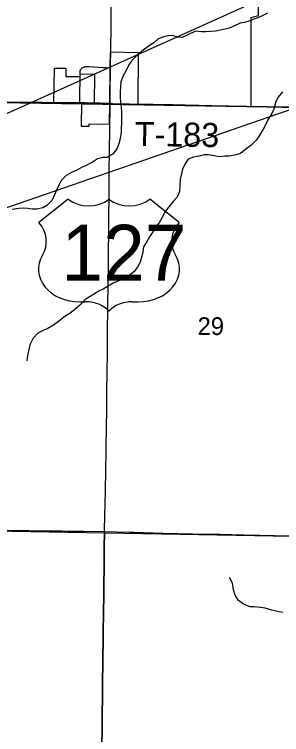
# Model space of a CAD drawing. Extents: x 0 to 34, y 0 to 22.
# Drawn here: x 6.718 to 7.346, y 15.064 to 16.761 of the extents above; entities that cross this region are included whole.
import ezdxf

# ---------------------------------------------------------------- set-up
doc = ezdxf.new("R2010")
doc.units = 0
for name, color, linetype in [('GM_X_Corporation', 7, 'Continuous'), ('GM_X_Minor_River', 7, 'Continuous'), ('GM_X_Section_Text', 7, 'Continuous'), ('GM_X_State_Route', 7, 'Continuous'), ('GM_X_Township_Road', 7, 'Continuous'), ('GM_X_Township_Road_Text', 7, 'Continuous'), ('GM_X_US_Location', 7, 'Continuous'), ('GM_X_US_Route', 7, 'Continuous'), ('GM_X_US_Shield', 7, 'Continuous'), ('SH_Data', 7, 'Continuous')]:
    doc.layers.add(name, color=color, linetype=linetype)

msp = doc.modelspace()

# ---------------------------------------------------------------- linework, layer by layer
at = {"layer": 'GM_X_Corporation'}
for points in [[(6.7004, 17.5689), (7.7016, 17.5373), (7.6999, 16.5369), (6.6829, 16.5538)], [(6.6829, 16.5538), (7.6999, 16.5369), (7.6779, 15.5253), (6.6666, 15.5439)]]:
    msp.add_lwpolyline(points, close=True, dxfattribs=at)
msp.add_lwpolyline([(6.6248, 16.5554), (6.8105, 16.5532), (6.8118, 16.6347), (6.839, 16.6342), (6.8387, 16.6152), (6.865, 16.6148), (6.8722, 16.6146), (6.8723, 16.621), (6.906, 16.6204), (6.905, 16.5515), (6.8756, 16.552), (6.875, 16.498), (6.8939, 16.4977), (6.894, 16.5034), (6.9414, 16.5025), (6.9419, 16.5525), (6.943, 16.6361), (6.9435, 16.6727), (7.0088, 16.6713), (7.0085, 16.5495), (7.2751, 16.5441), (7.2751, 16.7536), (7.2917, 16.7587), (7.2924, 16.7953)], dxfattribs=at)
at = {"layer": 'GM_X_Minor_River'}
for points in [[(7.313, 16.7641), (7.3004, 16.7579), (7.2908, 16.7535), (7.2809, 16.7499), (7.2713, 16.7463), (7.2588, 16.7424), (7.2492, 16.7403), (7.2355, 16.7345), (7.2229, 16.729), (7.2133, 16.7266), (7.2015, 16.7242), (7.1905, 16.7217), (7.1798, 16.7208), (7.1681, 16.7203), (7.1571, 16.7205), (7.1438, 16.7215), (7.1255, 16.7131), (7.1121, 16.7065), (7.1019, 16.7079), (7.089, 16.7116), (7.0788, 16.711), (7.0685, 16.7085), (7.0555, 16.7027), (7.0459, 16.6946), (7.0328, 16.6857), (7.0205, 16.6772), (7.0085, 16.6665), (6.9938, 16.6523), (6.9872, 16.6422), (6.9805, 16.6291), (6.9734, 16.6163), (6.9679, 16.6027), (6.9672, 16.591), (6.9666, 16.5781), (6.9668, 16.566), (6.9677, 16.5534), (6.9686, 16.5424), (6.9699, 16.5299), (6.97, 16.5173), (6.9697, 16.5044), (6.9692, 16.4942), (6.9686, 16.4836), (6.9676, 16.4738), (6.9639, 16.4587), (6.9587, 16.4443), (6.9498, 16.4331), (6.936, 16.4243), (6.9261, 16.4237), (6.9135, 16.4213), (6.9016, 16.4128), (6.8867, 16.4051), (6.8771, 16.4015), (6.8645, 16.3946), (6.8522, 16.3884), (6.8396, 16.3818), (6.8276, 16.3695), (6.8221, 16.359), (6.8169, 16.3469), (6.8122, 16.336), (6.8062, 16.3233), (6.7942, 16.3106), (6.7843, 16.3055), (6.7702, 16.3023), (6.7596, 16.3025), (6.749, 16.3043), (6.738, 16.3049), (6.7285, 16.3039), (6.7121, 16.3016)], [(7.3489, 16.579), (7.338, 16.5663), (7.3329, 16.5562), (7.328, 16.5377), (7.3236, 16.5275), (7.3142, 16.5125), (7.3063, 16.4964), (7.3005, 16.4866), (7.2934, 16.475), (7.2868, 16.4649), (7.274, 16.4526), (7.2625, 16.4441), (7.2494, 16.4334), (7.2364, 16.4294), (7.2227, 16.427), (7.2132, 16.4272), (7.2011, 16.4256), (7.1871, 16.4277), (7.1742, 16.4303), (7.164, 16.4305), (7.1526, 16.4273), (7.1392, 16.4245), (7.1262, 16.4198), (7.1177, 16.4071), (7.1133, 16.3969), (7.11, 16.3826)], [(7.11, 16.3826), (7.1075, 16.3724), (7.1072, 16.3584), (7.1062, 16.3443), (7.1006, 16.3304), (7.091, 16.3207), (7.0812, 16.3076), (7.0711, 16.2942), (7.066, 16.2844), (7.0589, 16.2717), (7.0519, 16.2619), (7.0355, 16.2372), (7.0284, 16.2248), (7.0214, 16.2136), (7.02, 16.2015), (7.0175, 16.1913), (7.0139, 16.1773), (7.0076, 16.1657), (6.9994, 16.1556), (6.9867, 16.1456), (6.9741, 16.139), (6.9633, 16.1332), (6.9503, 16.1277), (6.9369, 16.1204), (6.9262, 16.1138), (6.9166, 16.109), (6.9062, 16.1032), (6.8959, 16.0969), (6.8836, 16.0888), (6.8716, 16.0762), (6.8593, 16.0654), (6.8462, 16.0558), (6.8362, 16.0492), (6.8216, 16.0377), (6.81, 16.0292), (6.7966, 16.0215), (6.7866, 16.0171), (6.7732, 16.0102), (6.762, 15.9983), (6.7541, 15.9829), (6.7513, 15.9719), (6.7487, 15.9579), (6.7473, 15.9447)], [(7.2333, 15.4054), (7.2305, 15.4213), (7.224, 15.4347)], [(7.3494, 15.3519), (7.3366, 15.3544), (7.3234, 15.3577), (7.3079, 15.3618), (7.2969, 15.3639), (7.2818, 15.365), (7.2723, 15.3652), (7.258, 15.3707), (7.2453, 15.3805), (7.2372, 15.3931), (7.2333, 15.4054)]]:
    msp.add_lwpolyline(points, dxfattribs=at)
at = {"layer": 'GM_X_State_Route'}
msp.add_line((6.9423, 16.5018), (6.9428, 16.5344), dxfattribs=at)
for points in [[(6.9456, 16.7596), (6.9456, 16.7606), (6.9457, 16.7839), (6.9458, 16.7879)], [(6.9443, 16.6727), (6.9445, 16.6912), (6.945, 16.7184), (6.9452, 16.7457), (6.9456, 16.7596)], [(6.9438, 16.6354), (6.9439, 16.6432), (6.9443, 16.6717), (6.9443, 16.6727)], [(6.9428, 16.5518), (6.9428, 16.5537), (6.9432, 16.5885), (6.9437, 16.622), (6.9438, 16.6354)], [(6.9428, 16.5344), (6.9428, 16.5394), (6.9428, 16.5518)], [(6.9389, 16.1755), (6.9389, 16.1785), (6.94, 16.2717), (6.9402, 16.2984), (6.9405, 16.3177), (6.9407, 16.3631), (6.9409, 16.373), (6.9409, 16.4017), (6.9413, 16.4296), (6.9416, 16.451), (6.942, 16.4794), (6.9422, 16.4977), (6.9423, 16.5018)], [(6.9379, 16.0956), (6.938, 16.1045), (6.9389, 16.1755)], [(6.9296, 15.5426), (6.9306, 15.5826), (6.9311, 15.6043), (6.9325, 15.6823), (6.9335, 15.7364), (6.9344, 15.793), (6.9348, 15.8238), (6.9352, 15.8524), (6.9355, 15.8769), (6.936, 15.9136), (6.9365, 15.9685), (6.9368, 15.9973), (6.9371, 16.0273), (6.9376, 16.056), (6.9379, 16.0956)], [(6.675, 15.5461), (6.701, 15.5459), (6.7352, 15.5455), (6.7514, 15.545), (6.7657, 15.5447), (6.7959, 15.5444), (6.8145, 15.5442), (6.8298, 15.5441)], [(6.8298, 15.5441), (6.837, 15.544), (6.88, 15.5437), (6.9296, 15.5426)], [(6.9296, 15.5426), (6.9292, 15.504), (6.9286, 15.4555), (6.9281, 15.4219), (6.9279, 15.3859), (6.9275, 15.3598), (6.9258, 15.2342), (6.9253, 15.1863), (6.9239, 15.0781), (6.9236, 15.0402), (6.923, 14.9967), (6.9221, 14.9352), (6.9218, 14.8979), (6.9215, 14.8823), (6.921, 14.8425), (6.9207, 14.817), (6.9205, 14.7947), (6.9203, 14.7804)]]:
    msp.add_lwpolyline(points, dxfattribs=at)
at = {"layer": 'GM_X_Township_Road'}
msp.add_line((6.8718, 16.5535), (6.8758, 16.5535), dxfattribs=at)
for points in [[(6.8722, 16.6139), (6.8722, 16.6252), (6.8725, 16.6276), (6.8728, 16.6289), (6.8732, 16.63), (6.8736, 16.6308), (6.874, 16.6316), (6.8748, 16.6327), (6.8756, 16.6336), (6.8763, 16.6343), (6.8774, 16.6352)], [(6.8774, 16.6352), (6.8793, 16.6363), (6.8806, 16.637), (6.8817, 16.6375), (6.8827, 16.6378), (6.8834, 16.638), (6.885, 16.6382), (6.8871, 16.6384), (6.8933, 16.6384), (6.9039, 16.6379), (6.9268, 16.6362), (6.9336, 16.6359), (6.9438, 16.6354)], [(6.8718, 16.5535), (6.8718, 16.5593), (6.8718, 16.5768), (6.8722, 16.6055), (6.8722, 16.6139)], [(6.6248, 16.5547), (6.6387, 16.5547), (6.6598, 16.5547), (6.7003, 16.5546), (6.7394, 16.5545), (6.7833, 16.5541), (6.8106, 16.5539)], [(6.8106, 16.5539), (6.8442, 16.5536), (6.8718, 16.5535)], [(6.8758, 16.5535), (6.8836, 16.5534), (6.9052, 16.5528), (6.9061, 16.5528)], [(6.9061, 16.5528), (6.9123, 16.5527), (6.9198, 16.5526), (6.9383, 16.5519), (6.9428, 16.5518)], [(6.9428, 16.5518), (6.9486, 16.5512), (6.9528, 16.5509), (6.9573, 16.5507), (6.9883, 16.5502), (7.0085, 16.5499)], [(7.0085, 16.5499), (7.016, 16.5497), (7.044, 16.5494), (7.0906, 16.5486), (7.1192, 16.548), (7.1514, 16.5472), (7.1833, 16.5467), (7.2581, 16.545), (7.2752, 16.5446)], [(7.2752, 16.5446), (7.3029, 16.5439), (7.3259, 16.5435), (7.3477, 16.5429), (7.4055, 16.5418), (7.4602, 16.5405), (7.5248, 16.5387)]]:
    msp.add_lwpolyline(points, dxfattribs=at)
at = {"layer": 'GM_X_US_Route'}
for p, q in [((6.9423, 16.5018), (6.9428, 16.5344)), ((6.9296, 15.5426), (6.988, 15.5414))]:
    msp.add_line(p, q, dxfattribs=at)
for points in [[(6.9456, 16.7596), (6.9456, 16.7606), (6.9457, 16.7839), (6.9458, 16.7879)], [(6.9443, 16.6727), (6.9445, 16.6912), (6.945, 16.7184), (6.9452, 16.7457), (6.9456, 16.7596)], [(6.9438, 16.6354), (6.9439, 16.6432), (6.9443, 16.6717), (6.9443, 16.6727)], [(6.9428, 16.5518), (6.9428, 16.5537), (6.9432, 16.5885), (6.9437, 16.622), (6.9438, 16.6354)], [(6.9428, 16.5344), (6.9428, 16.5394), (6.9428, 16.5518)], [(6.9389, 16.1755), (6.9389, 16.1785), (6.94, 16.2717), (6.9402, 16.2984), (6.9405, 16.3177), (6.9407, 16.3631), (6.9409, 16.373), (6.9409, 16.4017), (6.9413, 16.4296), (6.9416, 16.451), (6.942, 16.4794), (6.9422, 16.4977), (6.9423, 16.5018)], [(6.9379, 16.0956), (6.938, 16.1045), (6.9389, 16.1755)], [(6.9296, 15.5426), (6.9306, 15.5826), (6.9311, 15.6043), (6.9325, 15.6823), (6.9335, 15.7364), (6.9344, 15.793), (6.9348, 15.8238), (6.9352, 15.8524), (6.9355, 15.8769), (6.936, 15.9136), (6.9365, 15.9685), (6.9368, 15.9973), (6.9371, 16.0273), (6.9376, 16.056), (6.9379, 16.0956)], [(6.675, 15.5461), (6.701, 15.5459), (6.7352, 15.5455), (6.7514, 15.545), (6.7657, 15.5447), (6.7959, 15.5444), (6.8145, 15.5442), (6.8298, 15.5441)], [(6.8298, 15.5441), (6.837, 15.544), (6.88, 15.5437), (6.9296, 15.5426)], [(6.9203, 14.7804), (6.9205, 14.7947), (6.9207, 14.817), (6.921, 14.8425), (6.9215, 14.8823), (6.9218, 14.8979), (6.9221, 14.9352), (6.923, 14.9967), (6.9236, 15.0402), (6.9239, 15.0781), (6.9253, 15.1863), (6.9258, 15.2342), (6.9275, 15.3598), (6.9279, 15.3859), (6.9281, 15.4219), (6.9286, 15.4555), (6.9292, 15.504), (6.9296, 15.5426)], [(6.988, 15.5414), (6.9991, 15.5412), (7.068, 15.5392), (7.137, 15.5374), (7.201, 15.5362), (7.2582, 15.535), (7.403, 15.5321)]]:
    msp.add_lwpolyline(points, dxfattribs=at)
at = {"layer": 'GM_X_US_Shield'}
for p, q in [((6.8441, 16.3259), (6.7754, 16.2709)), ((7.105, 16.2709), (7.0363, 16.3259)), ((6.8716, 16.0842), (6.8853, 16.0842)), ((6.9951, 16.0842), (7.0089, 16.0842))]:
    msp.add_line(p, q, dxfattribs=at)
for centre, major_axis, start_param, end_param in [((6.8922, 16.3651), (-0.0687, 0), 0.795399, 2.346194), ((6.9883, 16.3651), (-0.0687, 0), 0.795399, 2.346194), ((6.6967, 16.2268), (0.0961, 0), 5.838949, 6.894067), ((7.1838, 16.2268), (-0.0961, 0), 5.672304, 6.727422), ((6.8705, 16.1611), (0.0961, 0), 2.702327, 4.723529), ((7.01, 16.1611), (-0.0961, 0), 1.559657, 3.580859), ((6.8853, 16.0292), (-0.0687, 0), 3.785094, 4.712389), ((6.9951, 16.0292), (-0.0687, 0), 4.712389, 5.639684)]:
    msp.add_ellipse(centre, major_axis=major_axis, ratio=0.8, start_param=start_param, end_param=end_param, dxfattribs=at)
at = {"layer": 'SH_Data'}
msp.add_lwpolyline([(4.574, 15.5703), (9.2813, 17.2011), (9.2813, 17.6911)], close=True, dxfattribs=at)

# ---------------------------------------------------------------- texts
at = {"layer": 'GM_X_Section_Text'}
msp.add_text('29', height=0.04186, rotation=0, dxfattribs=at).set_placement((7.1487, 16.0058))
at = {"layer": 'GM_X_Township_Road_Text'}
msp.add_text('T-183', height=0.05682, rotation=359.1779, dxfattribs=at).set_placement((7.0007, 16.4513))
at = {"layer": 'GM_X_US_Location'}
for s in ['0', '/']:
    msp.add_text(s, height=0.000189, dxfattribs=at).set_placement((6.9403, 16.1994))
msp.add_text('127', height=0.000189, rotation=0, dxfattribs=at).set_placement((6.8821, 16.1602))
at = {"layer": 'GM_X_US_Shield'}
msp.add_text('127', height=0.13184, dxfattribs=at).set_placement((6.8283, 16.1336))

doc.saveas('drawing.dxf')
